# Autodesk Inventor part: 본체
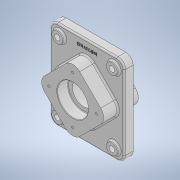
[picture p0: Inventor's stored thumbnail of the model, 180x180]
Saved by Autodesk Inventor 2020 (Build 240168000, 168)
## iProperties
Created: 2021-07
Part Number: 본체
Material: 일반
Document SubType Name: Modeling
Designer: Owner
Density: 1 g/cm^3
Appearance: 기본값
Mass: 807.977 g
Surface Area: 961.758 cm^2
Volume: 807.977 cm^3
Author: Owner
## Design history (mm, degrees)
sketch "스케치1"
  geometry: L1 (-75, 90)-(75, 90); L2 (75, 90)-(75, -90); L3 (75, -90)-(-75, -90); L4 (-75, -90)-(-75, 90); L5 (-75, 90)-(75, -90); L6 (75, 90)-(-75, -90); 1 further point
  constraints: 12 end point, 2 midpoint, 2 parallel, 1 horizontal, 1 perpendicular
  dimensions: "d0" = 150 distance of L2.end L3.end; "d1" = 180 distance of L1.end L2.end
extrude "돌출1" new body sketch "스케치1" stored distance "d2" = 18; taper "d3" = 0 deg
sketch "스케치2"
  geometry: L1 (0, 70.711)-(-70.711, 0); L2 (-70.711, 0)-(0, -70.711); L3 (0, -70.711)-(70.711, 0); L4 (70.711, 0)-(0, 70.711); L5 (75, -90)-(75, 90) reference; L6 (-75, 90)-(-75, -90) reference; L7 (-75, -90)-(75, -90) reference; 5 further points
  constraints: 8 end point, 4 midpoint, 2 horizontal alignment, 2 parallel, 2 perpendicular, 2 vertical alignment
  dimensions: "d4" = 100 distance of L2.end L3.end
extrude "돌출2" join sketch "스케치2" distance "d5" = 29; taper "d6" = 0 deg
fillet "모깎기1" dims "d7" = 20
fillet "모깎기2" dims "d8" = 3
sketch "스케치3"
  geometry: C1 r 31 at (0, 0); 1 further point
  constraints: 1 centre point, 1 coincident
  dimensions: "d9" = 62 diameter of C1
extrude "돌출3" cut sketch "스케치3" distance "d10" = 22; taper "d11" = 0 deg
sketch "스케치4"
  geometry: C1 r 22.5 at (0, 0); 1 further point
  constraints: 1 centre point, 1 coincident
  dimensions: "d12" = 45 diameter of C1
sketch "스케치5"
  geometry: L1 (0, 70.711)-(70.711, 0); L2 (70.711, 0)-(0, -70.711); L3 (0, -70.711)-(-70.711, 0); L4 (-70.711, 0)-(0, 70.711); L5 (75, -90)-(75, 90) reference; L6 (-75, 90)-(-75, -90) reference; L7 (75, 90)-(-75, 90) reference; L8 (-75, -90)-(75, -90) reference; 5 further points
  constraints: 8 end point, 4 midpoint, 2 horizontal alignment, 2 parallel, 2 vertical alignment, 1 perpendicular
  dimensions: "d13" = 100 distance of L3.end L1.start
extrude "돌출4" join sketch "스케치5" distance "d14" = 23; taper "d15" = 0 deg
extrude "돌출5" cut sketch "스케치4" distance "d16" = 26; taper "d17" = 0 deg
fillet "모깎기3" dims "d18" = 20
sketch "스케치6"
  geometry: C1 r 31 at (0, 0); 1 further point
  constraints: 1 centre point, 1 coincident
  dimensions: "d19" = 62 diameter of C1
extrude "돌출6" cut sketch "스케치6" distance "d20" = 22; taper "d21" = 0 deg
fillet "모깎기4" dims "d22" = 15
fillet "모깎기5" dims "d23" = 3
fillet "모깎기6" dims "d24" = 3
sketch "스케치7"
  geometry: L1 (-75, 75)-(-75, -75) reference; L2 (60, 90)-(-60, 90) reference; C1 r 11 at (-55, 70); C2 r 11 at (55, 70); 1 further point
  constraints: 2 centre point, 1 horizontal alignment
  dimensions: "d28" = 22 diameter of C1; "d29" = 22 diameter of C2; "d30" = 110 distance of C1.centre C2.centre; "d31" = 20 distance from line of L1 C1.centre; "d32" = 20 distance from line of L2 C1.centre
extrude "돌출7" join sketch "스케치7" distance "d33" = 5; taper "d34" = 0 deg
sketch "스케치8"
  geometry: C1 r 11 at (0, 0) reference; 2 further points
  constraints: 1 coincident
hole "구멍1" sketch "스케치8" at (0, 0) diameter "d35" = 11; stored, may be unused: countersink angle "d39" = 90 deg, drill point angle "d41" = 0 deg; dims "d36" = 6, "d37" = 4, "d38" = 2, "d40" = 23
sketch "스케치9"
  geometry: C1 r 11 at (0, 0) reference; 2 further points
  constraints: 1 coincident
hole "구멍2" sketch "스케치9" at (0, 0) diameter "d42" = 11; stored, may be unused: countersink angle "d46" = 90 deg, drill point angle "d48" = 0 deg; dims "d43" = 6, "d44" = 4, "d45" = 2, "d47" = 23
sketch "스케치10"
  geometry: C1 r 11 at (0, 0) reference; 2 further points
  constraints: 1 coincident
hole "구멍3" sketch "스케치10" at (0, 0) diameter "d49" = 11; stored, may be unused: countersink angle "d53" = 90 deg, drill point angle "d55" = 0 deg; dims "d50" = 6, "d51" = 4, "d52" = 2, "d54" = 23
sketch "스케치11"
  geometry: C1 r 11 at (0, 0) reference; 2 further points
  constraints: 1 coincident
hole "구멍4" sketch "스케치11" at (0, 0) diameter "d56" = 11; stored, may be unused: countersink angle "d60" = 90 deg, drill point angle "d62" = 0 deg; dims "d57" = 6, "d58" = 4, "d59" = 2, "d61" = 23
fillet "모깎기7" dims "d63" = 3
sketch "스케치12"
  geometry: 2 further points
  constraints: 1 vertical alignment
  dimensions: "d64" = 48 distance of point (0, 0) point (0, 48)
hole "구멍5" sketch "스케치12" at (0, 48) diameter "d65" = 4.917; stored, may be unused: countersink angle "d69" = 90 deg, drill point angle "d71" = 118 deg; dims "d66" = 10, "d67" = 4, "d68" = 2, "d70" = 13
sketch "스케치13"
  geometry: L1 (60, 90)-(-60, 90) reference; 2 further points
  constraints: 1 vertical alignment, 1 other
  dimensions: "d75" = 15 distance from line of L1 point (0, 75)
feature "엠보싱1" sketch "스케치13" dims "d0" = 150, "d1" = 180, "d76" = 0.5, "d77" = 0
fillet "모깎기8" dims "d78" = 1
chamfer "모따기1" distance "d79" = 1; stored, may be unused: second distance "d80" = 2, angle "d81" = 45 deg
sketch "스케치14"
  geometry: 2 further points
  constraints: 1 vertical alignment
  dimensions: "d82" = 48 distance of point (0, 0) point (0, 48)
hole "구멍6" sketch "스케치14" at (0, 48) diameter "d83" = 4.917; stored, may be unused: countersink angle "d87" = 90 deg, drill point angle "d89" = 118 deg; dims "d84" = 10, "d85" = 4, "d86" = 2, "d88" = 13
node "솔리드1"
mirror "미러1"
pattern_circular "원형 패턴1" dims angle "d73" = 360 deg
pattern_circular "원형 패턴2" dims angle "d91" = 360 deg
feature "A9D066F2-1C7D-4E18-AEED-F7BC21143FA4" dims "d35" = 11, "d36" = 6, "d37" = 4, "d38" = 2, "d39" = 90 deg, "d40" = 23, "d41" = 0
